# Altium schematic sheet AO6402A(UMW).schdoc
size 127 x 101 mm
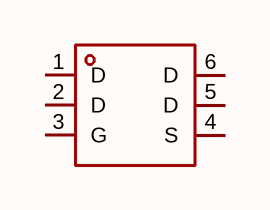
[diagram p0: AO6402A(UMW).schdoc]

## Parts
Q?  ao6402a(umw)  [SOT-23-6_L2.9-W1.6-P0.95-LS2.8-BR]  (value not drawn)

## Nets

Not connected (* = marked no-connect by the designer): Q? 1(D) 2(D) 3(G) 4(S) 5(D) 6(D)

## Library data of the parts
Q? = ao6402a(umw): 漏源电压(Vdss):30V;连续漏极电流(Id):7.5A;导通电阻(RDS(on)):17.3mΩ@10V;耗散功率(Pd):2W;阈值电压(Vgs(th)):2.1V@250uA;; Manufacturer: UMW(友台半导体); AddInBom: yes; ModelId: 18da8f6c14a34920b3e136b5c401a119; ModelName: SOT-23-6_L2.9-W1.6-H1.5-LS2.8-P0.95; ModelTransform: 110.73671,114.173,0,180,0,0,0.001,-0.003,0; Drain to Source Voltage: 30V; Current - Continuous Drain(Id): 7.5A; Pd - Power Dissipation: 2W; Gate Charge(Qg): 7.2nC@10V; Input Capacitance(Ciss): 373pF; Reverse Transfer Capacitance (Crss@Vds): 41pF; Output Capacitance(Coss): 67pF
